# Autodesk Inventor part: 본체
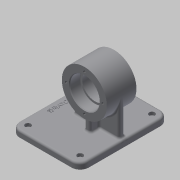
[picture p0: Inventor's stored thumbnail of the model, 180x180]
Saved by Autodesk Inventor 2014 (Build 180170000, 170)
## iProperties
Created: 2019-09
Part Number: 본체
Material: Generic
Document SubType Name: Modeling
Designer: kh
Density: 1 g/cm^3
Appearance: Default
Author: kh
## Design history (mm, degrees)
sketch "Sketch1"
  geometry: L1 (-51, -49)-(51, -49); L2 (63, -37)-(63, 37); L3 (51, 49)-(-51, 49); L4 (-63, 37)-(-63, -37); L5 (-63, -49)-(63, 49); L6 (63, -49)-(-63, 49); A1 r 12 centre (-51, 37) between (-51, 49) and (-63, 37); A2 r 12 centre (-51, -37) between (-63, -37) and (-51, -49); A3 r 12 centre (51, -37) between (51, -49) and (63, -37); A4 r 12 centre (51, 37) between (63, 37) and (51, 49); 1 further point
  constraints: 12 end point, 8 point on circle, 8 point on line, 8 tangent, 4 centre point, 3 equal radius, 2 midpoint, 2 parallel, 1 horizontal, 1 perpendicular
  dimensions: "d0" = 126 distance of L5.end L6.end; "d1" = 98 distance of L6.end L5.start; "d2" = 12 radius of A1
extrude "Extrusion1" new body sketch "Sketch1" distance "d3" = 9; taper "d4" = 0 deg
sketch "Sketch2"
  geometry: A1 r 12 centre (-51, 37) between (-51, 49) and (-63, 37) reference; A2 r 12 centre (51, 37) between (63, 37) and (51, 49) reference; A3 r 12 centre (51, -37) between (51, -49) and (63, -37) reference; A4 r 12 centre (-51, -37) between (-63, -37) and (-51, -49) reference; 5 further points
  constraints: 4 coincident
hole "Hole1" sketch "Sketch2" at (-51, 37), (51, 37), (-51, -37), (51, -37) diameter "d5" = 4.5; stored, may be unused: countersink angle "d9" = 90 deg, drill point angle "d11" = 118 deg; dims "d6" = 6, "d7" = 8, "d8" = 4.4, "d10" = 8
workplane "Work Plane3"
workplane "Work Plane4"
sketch "Sketch9"
  geometry: L1 (-12, -9)-(-12, 0) reference; L2 (-12, 0)-(114, 0) reference; L3 (114, 0)-(114, -9) reference; L4 (114, -9)-(-12, -9) reference; L5 (30, -91)-(72, -91); L6 (72, -91)-(72, -59); L7 (72, -59)-(30, -59); L8 (30, -59)-(30, -91); L9 (51, 0)-(51, -9); L10 (30, -80)-(45, -80); L11 (45, -80)-(45, -77); L12 (45, -77)-(57, -77); L13 (57, -77)-(57, -80); L14 (57, -80)-(72, -80)
  constraints: 20 end point, 4 parallel, 4 perpendicular, 2 point on line, 1 collinear, 1 horizontal, 1 midpoint, 2 other
  dimensions: "d52" = 64 diameter of L5 L7; "d53" = 59 vertical distance of L1.end L7.end; "d54" = 42 distance of L5.start L5.end; "d55" = 42 diameter of L10 L7; "d56" = 36 diameter of L12 L7; "d57" = 15 distance of L10.start L10.end
revolve "Revolution4" sketch "Sketch9" stored, may be unused: angle "d58" = 90 deg
sketch "Sketch10"
  geometry: C1 r 32 at (0, 0) reference; 2 further points
  constraints: 1 horizontal alignment
  dimensions: "d59" = 26 distance of point (26, 0) C1.centre
hole "Hole3" sketch "Sketch10" at (26, 0) diameter "d60" = 3.242; stored, may be unused: countersink angle "d64" = 90 deg, drill point angle "d66" = 118 deg; dims "d61" = 8, "d62" = 8, "d63" = 4.4, "d65" = 10
pattern_circular "Circular Pattern2" dims angle "d68" = 360 deg
mirror "Mirror2"
sketch "Sketch11"
  geometry: L1 (51, 49)-(-51, 49) reference; L2 (-51, -49)-(51, -49) reference; L3 (-4, 19)-(4, 19); L4 (4, 19)-(4, -45); L5 (4, -45)-(-4, -45); L6 (-4, -45)-(-4, 19); L7 (-17, -9)-(17, -9); L8 (17, -9)-(17, -17); L9 (17, -17)-(-17, -17); L10 (-17, -17)-(-17, -9); L11 (0, 0)-(0, 20.336); L12 (-17, -13)-(17, -13)
  constraints: 20 end point, 4 parallel, 3 perpendicular, 2 horizontal, 2 midpoint, 3 other
  dimensions: "d87" = 8 distance of L3.start L3.end; "d88" = 64 distance of L3.end L4.end; "d89" = 34 distance of L7.start L7.end; "d90" = 62 distance from line of L1 L12.end; "d91" = 8 distance of L9.end L7.start
fillet "Fillet1" dims "d83" = 0.3
chamfer "Chamfer1" distance "d84" = 1; stored, may be unused: second distance "d85" = 2, angle "d86" = 45 deg
extrude "Extrusion3" join sketch "Sketch11" stored distance "d92" = 9; taper "d93" = 0 deg
fillet "Fillet2" dims "d94" = 3
fillet "Fillet3" dims "d95" = 3
sketch "Sketch12"
  geometry: L1 (-20.739, 42.002)-(20.739, 42.002); L2 (20.739, 42.002)-(20.739, 35.998); L3 (20.739, 35.998)-(-20.739, 35.998); L4 (-20.739, 35.998)-(-20.739, 42.002); L5 (-20.739, 42.002)-(20.739, 35.998); L6 (-20.739, 35.998)-(20.739, 42.002); L7 (63, -37)-(63, 37) reference; L8 (51, 49)-(-51, 49) reference; 2 further points
  constraints: 4 end point, 1 midpoint, 2 other
  dimensions: "d96" = 10 distance from line of L8 point (0, 39); "d97" = 63 distance from line of point (0, 39) L7
emboss "Emboss1" sketch "Sketch12" dims "d0" = 126, "d1" = 98, "d2" = 12, "d98" = 0.5, "d99" = 0
body "Solid1"
node "Project Cut Edges5"
other parameters: "d42" = 28, "d51" = -62
